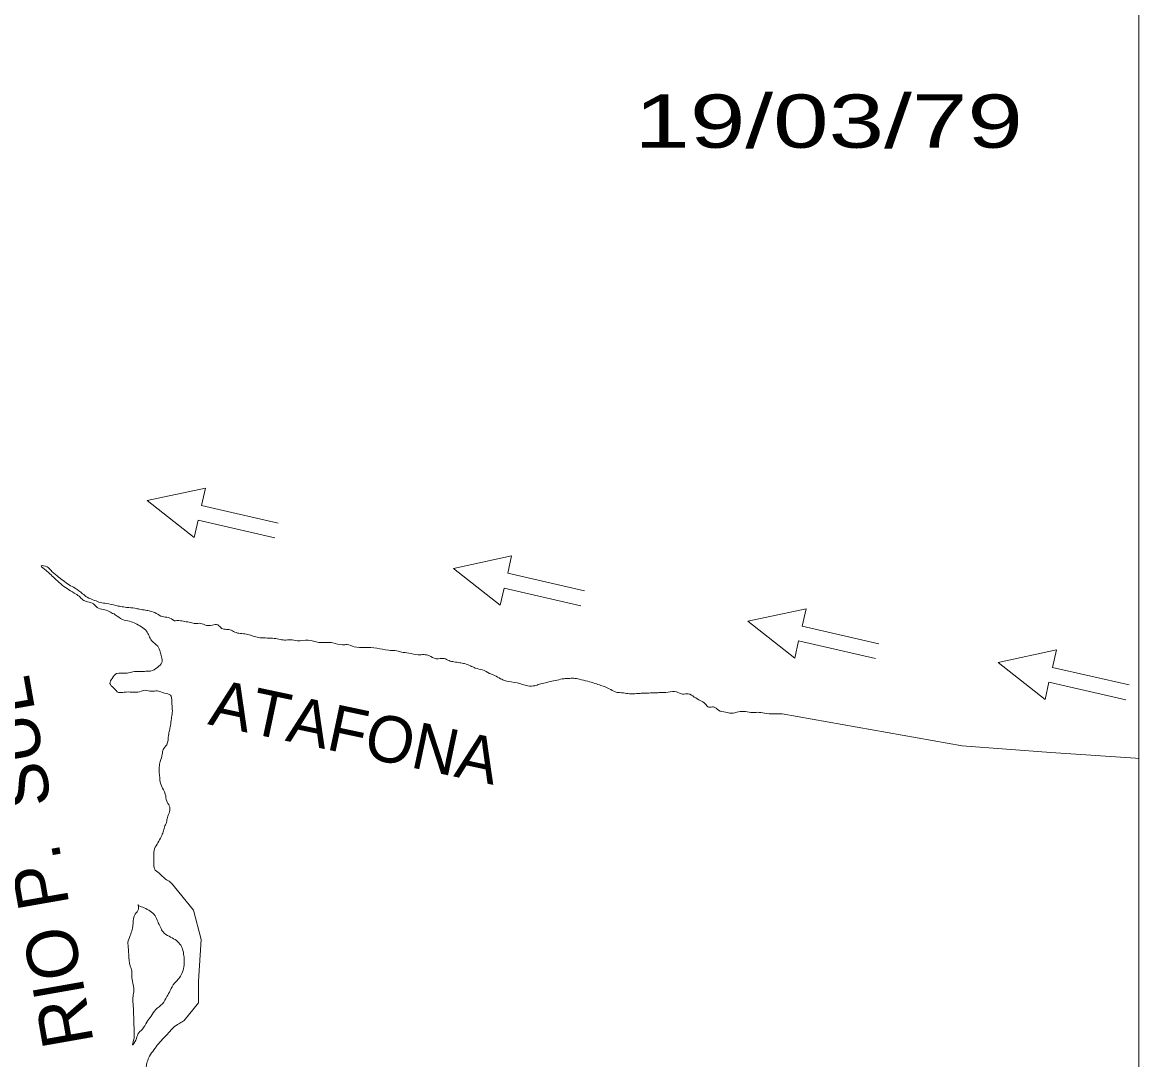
# Model space of a CAD drawing. Extents: x 3 to 328, y -131 to 329.
# Drawn here: x 112.96 to 161.12, y 21.7 to 66.48 of the extents above; entities that cross this region are included whole.
import ezdxf
from ezdxf.enums import TextEntityAlignment as Align

# ---------------------------------------------------------------- set-up
doc = ezdxf.new("R2010")
doc.units = 0
doc.header["$LTSCALE"] = 0.88
doc.layers.add('1', color=7, linetype='Continuous', lineweight=13)

msp = doc.modelspace()

# ---------------------------------------------------------------- linework, layer by layer
at = {"layer": '1'}
msp.add_line((117.96, 28.35), (117.96, 28.4), dxfattribs=at)
msp.add_lwpolyline([(35.23, 240.18), (161.12, 240.18), (161.12, -20.55), (35.23, -20.55)], close=True, dxfattribs=at)
msp.add_lwpolyline([(35.23, 240.18), (161.12, 240.18), (161.12, -20.55), (35.23, -20.55)], close=True, dxfattribs=at)
for points in [[(124, 44.87), (120.69, 45.63), (120.86, 46.38), (118.35, 45.84)], [(123.85, 44.23), (120.54, 44.99), (120.37, 44.25), (118.35, 45.84)], [(137.21, 41.94), (133.9, 42.7), (134.07, 43.45), (131.56, 42.91)], [(137.06, 41.3), (133.75, 42.06), (133.58, 41.32), (131.56, 42.91)], [(149.91, 39.66), (146.6, 40.42), (146.77, 41.17), (144.26, 40.63)], [(149.76, 39.02), (146.45, 39.78), (146.28, 39.04), (144.26, 40.63)], [(160.71, 37.88), (157.4, 38.64), (157.57, 39.39), (155.06, 38.85)], [(160.56, 37.24), (157.25, 38), (157.08, 37.26), (155.06, 38.85)], [(160.98, 34.72), (157.33, 34.96), (153.51, 35.25), (145.74, 36.64)], [(147.51, -20.55), (161.12, -20.55), (161.12, 34.71), (160.98, 34.72)], [(119.4, 29.32), (120.35, 28.16), (120.67, 26.89), (120.56, 25.1), (120.56, 24.16), (119.95, 23.39)], [(119.4, 29.32), (120.35, 28.16), (120.67, 26.89), (120.56, 25.1), (120.56, 24.16), (119.95, 23.39)]]:
    msp.add_lwpolyline(points, dxfattribs=at)
for points in [[(119.52, 40.65), (119.26, 40.79), (119, 40.83), (118.74, 40.97), (118.48, 41.07), (118.28, 41.11), (118.02, 41.15), (117.82, 41.19), (117.46, 41.23), (117.2, 41.27), (117, 41.31), (116.59, 41.4), (116.33, 41.44), (116.08, 41.53), (115.76, 41.67), (115.56, 41.82), (115.24, 42.06), (114.98, 42.2), (114.72, 42.39), (114.46, 42.59), (114.19, 42.83), (114.03, 42.98), (113.78, 43.02), (113.99, 42.82), (114.15, 42.68), (114.36, 42.48), (114.62, 42.24), (114.89, 42.04), (115.2, 41.85), (115.41, 41.71), (115.57, 41.56), (115.77, 41.47), (116.03, 41.38), (116.19, 41.23), (116.45, 41.14), (116.71, 41.05), (116.91, 40.95), (116.94, 40.94)], [(119.52, 40.65), (119.26, 40.79), (119, 40.83), (118.74, 40.97), (118.48, 41.07), (118.28, 41.11), (118.02, 41.15), (117.82, 41.19), (117.46, 41.23), (117.2, 41.27), (117, 41.31), (116.59, 41.4), (116.33, 41.44), (116.08, 41.53), (115.76, 41.67), (115.56, 41.82), (115.24, 42.06), (114.98, 42.2), (114.72, 42.39), (114.46, 42.59), (114.19, 42.83), (114.03, 42.98), (113.78, 43.02), (113.99, 42.82), (114.15, 42.68), (114.36, 42.48), (114.62, 42.24), (114.89, 42.04), (115.2, 41.85), (115.41, 41.71), (115.57, 41.56), (115.77, 41.47), (116.03, 41.38), (116.19, 41.23), (116.45, 41.14), (116.71, 41.05), (116.91, 40.95), (116.94, 40.94)], [(118.87, 29.75), (118.66, 29.95), (118.64, 30.2), (118.63, 30.51), (118.67, 30.81), (118.81, 31.07), (118.95, 31.33), (119.04, 31.54), (119.09, 31.74), (119.18, 31.95), (119.22, 32.16), (119.31, 32.41), (119.3, 32.67), (119.19, 32.87), (119.13, 33.17), (118.96, 33.52), (118.89, 33.87), (118.87, 34.33), (118.91, 34.58), (119, 34.89), (119.04, 35.09), (119.19, 35.3), (119.27, 35.71), (119.31, 35.92), (119.35, 36.12), (119.39, 36.43), (119.43, 36.68), (119.42, 36.99), (119.41, 37.19), (119.35, 37.44), (119.09, 37.53), (118.78, 37.62), (118.53, 37.61), (118.27, 37.65), (118.02, 37.59), (117.36, 37.57), (117.11, 37.56), (116.9, 37.75), (116.74, 37.95), (116.83, 38.16), (117.02, 38.37), (117.48, 38.39), (117.73, 38.45), (118.04, 38.46), (118.29, 38.47), (118.49, 38.48), (118.79, 38.64), (118.98, 38.85), (118.97, 39.1), (118.91, 39.31), (118.8, 39.55), (118.54, 39.8), (118.43, 40), (118.32, 40.2), (118.1, 40.39), (117.84, 40.53), (117.59, 40.63), (117.28, 40.71), (116.97, 40.91), (116.91, 40.95)], [(116.91, 40.95), (116.97, 40.91), (117.28, 40.71), (117.59, 40.63), (117.84, 40.53), (118.1, 40.39), (118.32, 40.2), (118.43, 40), (118.54, 39.8), (118.8, 39.55), (118.91, 39.31), (118.97, 39.1), (118.98, 38.85), (118.79, 38.64), (118.49, 38.48), (118.29, 38.47), (118.04, 38.46), (117.73, 38.45), (117.48, 38.39), (117.02, 38.37), (116.83, 38.16), (116.74, 37.95), (116.9, 37.75), (117.11, 37.56), (117.36, 37.57), (118.02, 37.59), (118.27, 37.65), (118.53, 37.61), (118.78, 37.62), (119.09, 37.53), (119.35, 37.44), (119.41, 37.19), (119.42, 36.99), (119.43, 36.68), (119.39, 36.43), (119.35, 36.12), (119.31, 35.92), (119.27, 35.71), (119.19, 35.3), (119.04, 35.09), (119, 34.89), (118.91, 34.58), (118.87, 34.33), (118.89, 33.87), (118.96, 33.52), (119.13, 33.17), (119.19, 32.87), (119.3, 32.67), (119.31, 32.41), (119.22, 32.16), (119.18, 31.95), (119.09, 31.74), (119.04, 31.54), (118.95, 31.33), (118.81, 31.07), (118.67, 30.81), (118.63, 30.51), (118.64, 30.2), (118.66, 29.95), (118.87, 29.75)], [(118.87, 29.75), (118.66, 29.95), (118.64, 30.2), (118.63, 30.51), (118.67, 30.81), (118.81, 31.07), (118.95, 31.33), (119.04, 31.54), (119.09, 31.74), (119.18, 31.95), (119.22, 32.16), (119.31, 32.41), (119.3, 32.67), (119.19, 32.87), (119.13, 33.17), (118.96, 33.52), (118.89, 33.87), (118.87, 34.33), (118.91, 34.58), (119, 34.89), (119.04, 35.09), (119.19, 35.3), (119.27, 35.71), (119.31, 35.92), (119.35, 36.12), (119.39, 36.43), (119.43, 36.68), (119.42, 36.99), (119.41, 37.19), (119.35, 37.44), (119.09, 37.53), (118.78, 37.62), (118.53, 37.61), (118.27, 37.65), (118.02, 37.59), (117.36, 37.57), (117.11, 37.56), (116.9, 37.75), (116.74, 37.95), (116.83, 38.16), (117.02, 38.37), (117.48, 38.39), (117.73, 38.45), (118.04, 38.46), (118.29, 38.47), (118.49, 38.48), (118.79, 38.64), (118.98, 38.85), (118.97, 39.1), (118.91, 39.31), (118.8, 39.55), (118.54, 39.8), (118.43, 40), (118.32, 40.2), (118.1, 40.39), (117.84, 40.53), (117.59, 40.63), (117.28, 40.71), (116.97, 40.91), (116.91, 40.95)], [(145.74, 36.64), (145.38, 36.63), (144.98, 36.66), (144.67, 36.7), (144.47, 36.69), (144.16, 36.73), (143.86, 36.72), (143.55, 36.66), (143.3, 36.7), (142.99, 36.79), (142.78, 36.93), (142.58, 36.92), (142.42, 37.07), (142.21, 37.21), (141.95, 37.36), (141.69, 37.5), (141.44, 37.49), (141.18, 37.58), (140.82, 37.57), (140.42, 37.55), (140.22, 37.54), (139.91, 37.53), (139.66, 37.52), (139.46, 37.51), (139.15, 37.5), (138.9, 37.54), (138.54, 37.58), (138.28, 37.72), (137.92, 37.86), (137.66, 37.95), (137.35, 38.04), (136.99, 38.13), (136.74, 38.17), (136.53, 38.16), (136.33, 38.15), (136.03, 38.09), (135.73, 38.03), (135.53, 37.97), (135.27, 37.91), (135.07, 37.85), (134.77, 37.84), (134.31, 37.97), (133.8, 38.06), (133.59, 38.15), (133.33, 38.29), (133.12, 38.38), (132.81, 38.53), (132.5, 38.61), (132.29, 38.71), (132.04, 38.8), (131.83, 38.84), (131.58, 38.88), (131.37, 38.93), (131.16, 39.02), (130.81, 39.01), (130.5, 39.15), (130.29, 39.19), (130.04, 39.18), (129.63, 39.26), (129.32, 39.3), (129.12, 39.35), (128.76, 39.38), (128.25, 39.47), (127.74, 39.5), (127.28, 39.53), (126.97, 39.62), (126.77, 39.61), (126.36, 39.7), (125.75, 39.72), (125.29, 39.81), (124.83, 39.79), (124.53, 39.83), (124.27, 39.82), (124.02, 39.86), (123.76, 39.9), (123.15, 39.93), (122.69, 40.06), (122.43, 40.1), (122.18, 40.14), (121.97, 40.24), (121.77, 40.28), (121.56, 40.32), (121.4, 40.47), (121.15, 40.46), (120.9, 40.45), (120.64, 40.54), (120.43, 40.53), (120.23, 40.58), (119.97, 40.62), (119.72, 40.66), (119.52, 40.65)], [(145.74, 36.64), (145.38, 36.63), (144.98, 36.66), (144.67, 36.7), (144.47, 36.69), (144.16, 36.73), (143.86, 36.72), (143.55, 36.66), (143.3, 36.7), (142.99, 36.79), (142.78, 36.93), (142.58, 36.92), (142.42, 37.07), (142.21, 37.21), (141.95, 37.36), (141.69, 37.5), (141.44, 37.49), (141.18, 37.58), (140.82, 37.57), (140.42, 37.55), (140.22, 37.54), (139.91, 37.53), (139.66, 37.52), (139.46, 37.51), (139.15, 37.5), (138.9, 37.54), (138.54, 37.58), (138.28, 37.72), (137.92, 37.86), (137.66, 37.95), (137.35, 38.04), (136.99, 38.13), (136.74, 38.17), (136.53, 38.16), (136.33, 38.15), (136.03, 38.09), (135.73, 38.03), (135.53, 37.97), (135.27, 37.91), (135.07, 37.85), (134.77, 37.84), (134.31, 37.97), (133.8, 38.06), (133.59, 38.15), (133.33, 38.29), (133.12, 38.38), (132.81, 38.53), (132.5, 38.61), (132.29, 38.71), (132.04, 38.8), (131.83, 38.84), (131.58, 38.88), (131.37, 38.93), (131.16, 39.02), (130.81, 39.01), (130.5, 39.15), (130.29, 39.19), (130.04, 39.18), (129.63, 39.26), (129.32, 39.3), (129.12, 39.35), (128.76, 39.38), (128.25, 39.47), (127.74, 39.5), (127.28, 39.53), (126.97, 39.62), (126.77, 39.61), (126.36, 39.7), (125.75, 39.72), (125.29, 39.81), (124.83, 39.79), (124.53, 39.83), (124.27, 39.82), (124.02, 39.86), (123.76, 39.9), (123.15, 39.93), (122.69, 40.06), (122.43, 40.1), (122.18, 40.14), (121.97, 40.24), (121.77, 40.28), (121.56, 40.32), (121.4, 40.47), (121.15, 40.46), (120.9, 40.45), (120.64, 40.54), (120.43, 40.53), (120.23, 40.58), (119.97, 40.62), (119.72, 40.66), (119.52, 40.65)], [(119.4, 29.32), (119.34, 29.37), (119.13, 29.51), (118.87, 29.75)], [(118.87, 29.75), (119.13, 29.51), (119.34, 29.37), (119.4, 29.32)], [(119.4, 29.32), (119.34, 29.37), (119.13, 29.51), (118.87, 29.75)], [(117.96, 28.4), (117.97, 28.2), (117.83, 27.99), (117.74, 27.58), (117.7, 27.32), (117.61, 27.06), (117.52, 26.76), (117.53, 26.55), (117.55, 26.25), (117.62, 25.74), (117.68, 25.54), (117.69, 25.24), (117.75, 24.94), (117.77, 24.63), (117.73, 24.38), (117.74, 24.12), (117.76, 23.72), (117.77, 23.41), (117.78, 23.11), (117.79, 22.86), (117.76, 22.55), (117.71, 22.34), (117.86, 22.55), (117.95, 22.81), (118.14, 23.02), (118.33, 23.33), (118.52, 23.59), (118.71, 23.86), (119.01, 24.12), (119.2, 24.43), (119.34, 24.69), (119.53, 25.01), (119.67, 25.16), (119.82, 25.37), (119.91, 25.63), (119.95, 25.94), (119.93, 26.19), (119.87, 26.49), (119.76, 26.69), (119.55, 26.89), (119.29, 27.03), (119.03, 27.22), (118.92, 27.42), (118.8, 27.67), (118.69, 27.92), (118.48, 28.11), (118.22, 28.26), (117.96, 28.35)], [(117.96, 28.4), (117.97, 28.2), (117.83, 27.99), (117.74, 27.58), (117.7, 27.32), (117.61, 27.06), (117.52, 26.76), (117.53, 26.55), (117.55, 26.25), (117.62, 25.74), (117.68, 25.54), (117.69, 25.24), (117.75, 24.94), (117.77, 24.63), (117.73, 24.38), (117.74, 24.12), (117.76, 23.72), (117.77, 23.41), (117.78, 23.11), (117.79, 22.86), (117.76, 22.55), (117.71, 22.34), (117.86, 22.55), (117.95, 22.81), (118.14, 23.02), (118.33, 23.33), (118.52, 23.59), (118.71, 23.86), (119.01, 24.12), (119.2, 24.43), (119.34, 24.69), (119.53, 25.01), (119.67, 25.16), (119.82, 25.37), (119.91, 25.63), (119.95, 25.94), (119.93, 26.19), (119.87, 26.49), (119.76, 26.69), (119.55, 26.89), (119.29, 27.03), (119.03, 27.22), (118.92, 27.42), (118.8, 27.67), (118.69, 27.92), (118.48, 28.11), (118.22, 28.26), (117.96, 28.35)], [(119.95, 23.39), (119.85, 23.34), (119.66, 23.23), (119.41, 23.02), (119.27, 22.86), (119.07, 22.65), (118.83, 22.39), (118.64, 22.13), (118.45, 21.86), (118.35, 21.61), (118.31, 21.4), (118.33, 21), (118.34, 20.69), (118.35, 20.44), (118.36, 20.24), (118.37, 20.03), (118.38, 19.73), (118.45, 19.48), (118.52, 19.02), (118.53, 18.82), (118.58, 18.62), (118.59, 18.42), (118.71, 18.07), (118.77, 17.81), (118.88, 17.56), (119.04, 17.37), (119.05, 17.16), (119.16, 16.97), (119.23, 16.71), (119.34, 16.52), (119.45, 16.27), (119.56, 16.02), (119.67, 15.77), (119.78, 15.52), (119.95, 15.27), (120.16, 15.02), (120.43, 14.68), (120.59, 14.43), (120.81, 14.19), (121.02, 14.04), (121.08, 13.84), (121.23, 13.69), (121.4, 13.45), (121.56, 13.25), (121.67, 13.05), (121.88, 12.83)], [(121.88, 12.83), (121.67, 13.05), (121.56, 13.25), (121.4, 13.45), (121.23, 13.69), (121.08, 13.84), (121.02, 14.04), (120.81, 14.19), (120.59, 14.43), (120.43, 14.68), (120.16, 15.02), (119.95, 15.27), (119.78, 15.52), (119.67, 15.77), (119.56, 16.02), (119.45, 16.27), (119.34, 16.52), (119.23, 16.71), (119.16, 16.97), (119.05, 17.16), (119.04, 17.37), (118.88, 17.56), (118.77, 17.81), (118.71, 18.07), (118.59, 18.42), (118.58, 18.62), (118.53, 18.82), (118.52, 19.02), (118.45, 19.48), (118.38, 19.73), (118.37, 20.03), (118.36, 20.24), (118.35, 20.44), (118.34, 20.69), (118.33, 21), (118.31, 21.4), (118.35, 21.61), (118.45, 21.86), (118.64, 22.13), (118.83, 22.39), (119.07, 22.65), (119.27, 22.86), (119.41, 23.02), (119.66, 23.23), (119.85, 23.34), (119.95, 23.39)]]:
    msp.add_spline(points, degree=3, dxfattribs=at)

# ---------------------------------------------------------------- texts
at = {"layer": '1', "width": 1.4}
msp.add_text('19/03/79', height=2.3, dxfattribs=at).set_placement((147.745, 61.07), align=Align.CENTER)
at = {"layer": '1'}
for s, height, rotation, p in [('RIO P.  SUL', 2.2, 100, (114.644, 30.414)), ('ATAFONA', 2, 348, (127.107, 34.878))]:
    msp.add_text(s, height=height, rotation=rotation, dxfattribs=at).set_placement(p, align=Align.CENTER)

doc.saveas('drawing.dxf')
